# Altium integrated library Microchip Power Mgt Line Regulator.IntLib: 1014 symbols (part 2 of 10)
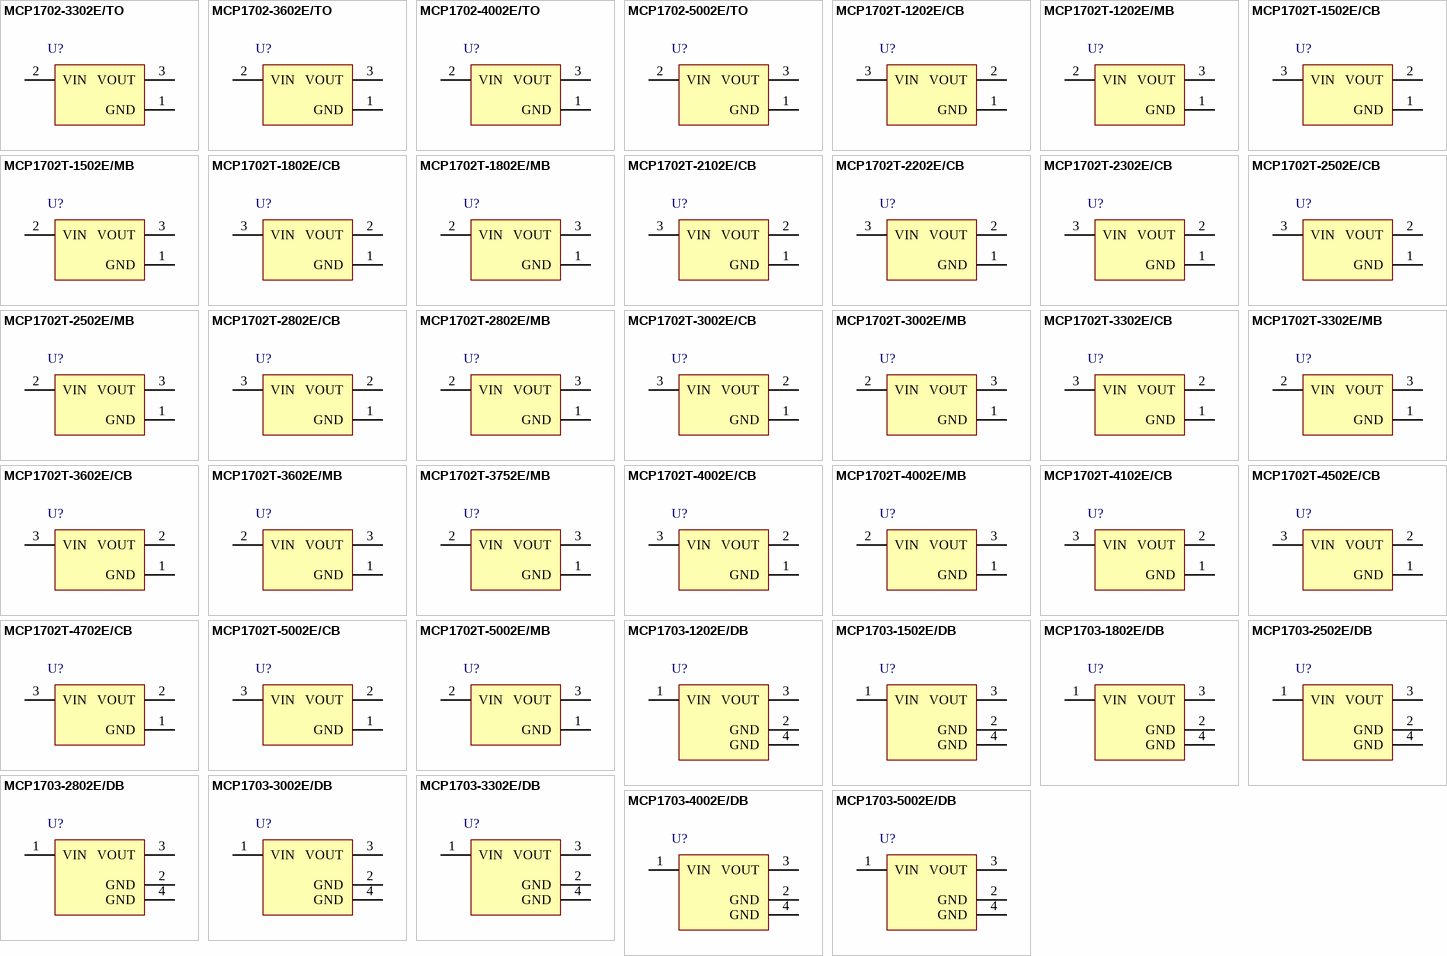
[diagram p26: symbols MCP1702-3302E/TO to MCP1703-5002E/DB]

## MCP1703-2502E/DB
designator U?
250 mA, 16V, Low Quiescent Current LDO Regulator, 3-Pin SOT-223, Extended Temperature
footprint SOT-223-DB3_N (SOT223, 4-Leads, Body 6.5x3.5mm, Pitch 2.3mm, Lead Span 7mm, IPC Medium Density)
footprint SOT-223-DB3_L (SOT223, 4-Leads, Body 6.5x3.5mm, Pitch 2.3mm, Lead Span 7mm, IPC High Density)
footprint SOT-223-DB3_M (SOT223, 4-Leads, Body 6.5x3.5mm, Pitch 2.3mm, Lead Span 7mm, IPC Low Density)
pins: 1 VIN (power), 2 GND (power), 3 VOUT (power), 4 GND (power)

## MCP1703-2802E/DB
designator U?
250 mA, 16V, Low Quiescent Current LDO Regulator, 3-Pin SOT-223, Extended Temperature
footprint SOT-223-DB3_N (SOT223, 4-Leads, Body 6.5x3.5mm, Pitch 2.3mm, Lead Span 7mm, IPC Medium Density)
footprint SOT-223-DB3_L (SOT223, 4-Leads, Body 6.5x3.5mm, Pitch 2.3mm, Lead Span 7mm, IPC High Density)
footprint SOT-223-DB3_M (SOT223, 4-Leads, Body 6.5x3.5mm, Pitch 2.3mm, Lead Span 7mm, IPC Low Density)
pins: 1 VIN (power), 2 GND (power), 3 VOUT (power), 4 GND (power)

## MCP1703-3002E/DB
designator U?
250 mA, 16V, Low Quiescent Current LDO Regulator, 3-Pin SOT-223, Extended Temperature
footprint SOT-223-DB3_N (SOT223, 4-Leads, Body 6.5x3.5mm, Pitch 2.3mm, Lead Span 7mm, IPC Medium Density)
footprint SOT-223-DB3_L (SOT223, 4-Leads, Body 6.5x3.5mm, Pitch 2.3mm, Lead Span 7mm, IPC High Density)
footprint SOT-223-DB3_M (SOT223, 4-Leads, Body 6.5x3.5mm, Pitch 2.3mm, Lead Span 7mm, IPC Low Density)
pins: 1 VIN (power), 2 GND (power), 3 VOUT (power), 4 GND (power)

## MCP1703-3302E/DB
designator U?
250 mA, 16V, Low Quiescent Current LDO Regulator, 3-Pin SOT-223, Extended Temperature
footprint SOT-223-DB3_N (SOT223, 4-Leads, Body 6.5x3.5mm, Pitch 2.3mm, Lead Span 7mm, IPC Medium Density)
footprint SOT-223-DB3_L (SOT223, 4-Leads, Body 6.5x3.5mm, Pitch 2.3mm, Lead Span 7mm, IPC High Density)
footprint SOT-223-DB3_M (SOT223, 4-Leads, Body 6.5x3.5mm, Pitch 2.3mm, Lead Span 7mm, IPC Low Density)
pins: 1 VIN (power), 2 GND (power), 3 VOUT (power), 4 GND (power)

## MCP1703-4002E/DB
designator U?
250 mA, 16V, Low Quiescent Current LDO Regulator, 3-Pin SOT-223, Extended Temperature
footprint SOT-223-DB3_N (SOT223, 4-Leads, Body 6.5x3.5mm, Pitch 2.3mm, Lead Span 7mm, IPC Medium Density)
footprint SOT-223-DB3_L (SOT223, 4-Leads, Body 6.5x3.5mm, Pitch 2.3mm, Lead Span 7mm, IPC High Density)
footprint SOT-223-DB3_M (SOT223, 4-Leads, Body 6.5x3.5mm, Pitch 2.3mm, Lead Span 7mm, IPC Low Density)
pins: 1 VIN (power), 2 GND (power), 3 VOUT (power), 4 GND (power)

## MCP1703-5002E/DB
designator U?
250 mA, 16V, Low Quiescent Current LDO Regulator, 3-Pin SOT-223, Extended Temperature
footprint SOT-223-DB3_N (SOT223, 4-Leads, Body 6.5x3.5mm, Pitch 2.3mm, Lead Span 7mm, IPC Medium Density)
footprint SOT-223-DB3_L (SOT223, 4-Leads, Body 6.5x3.5mm, Pitch 2.3mm, Lead Span 7mm, IPC High Density)
footprint SOT-223-DB3_M (SOT223, 4-Leads, Body 6.5x3.5mm, Pitch 2.3mm, Lead Span 7mm, IPC Low Density)
pins: 1 VIN (power), 2 GND (power), 3 VOUT (power), 4 GND (power)

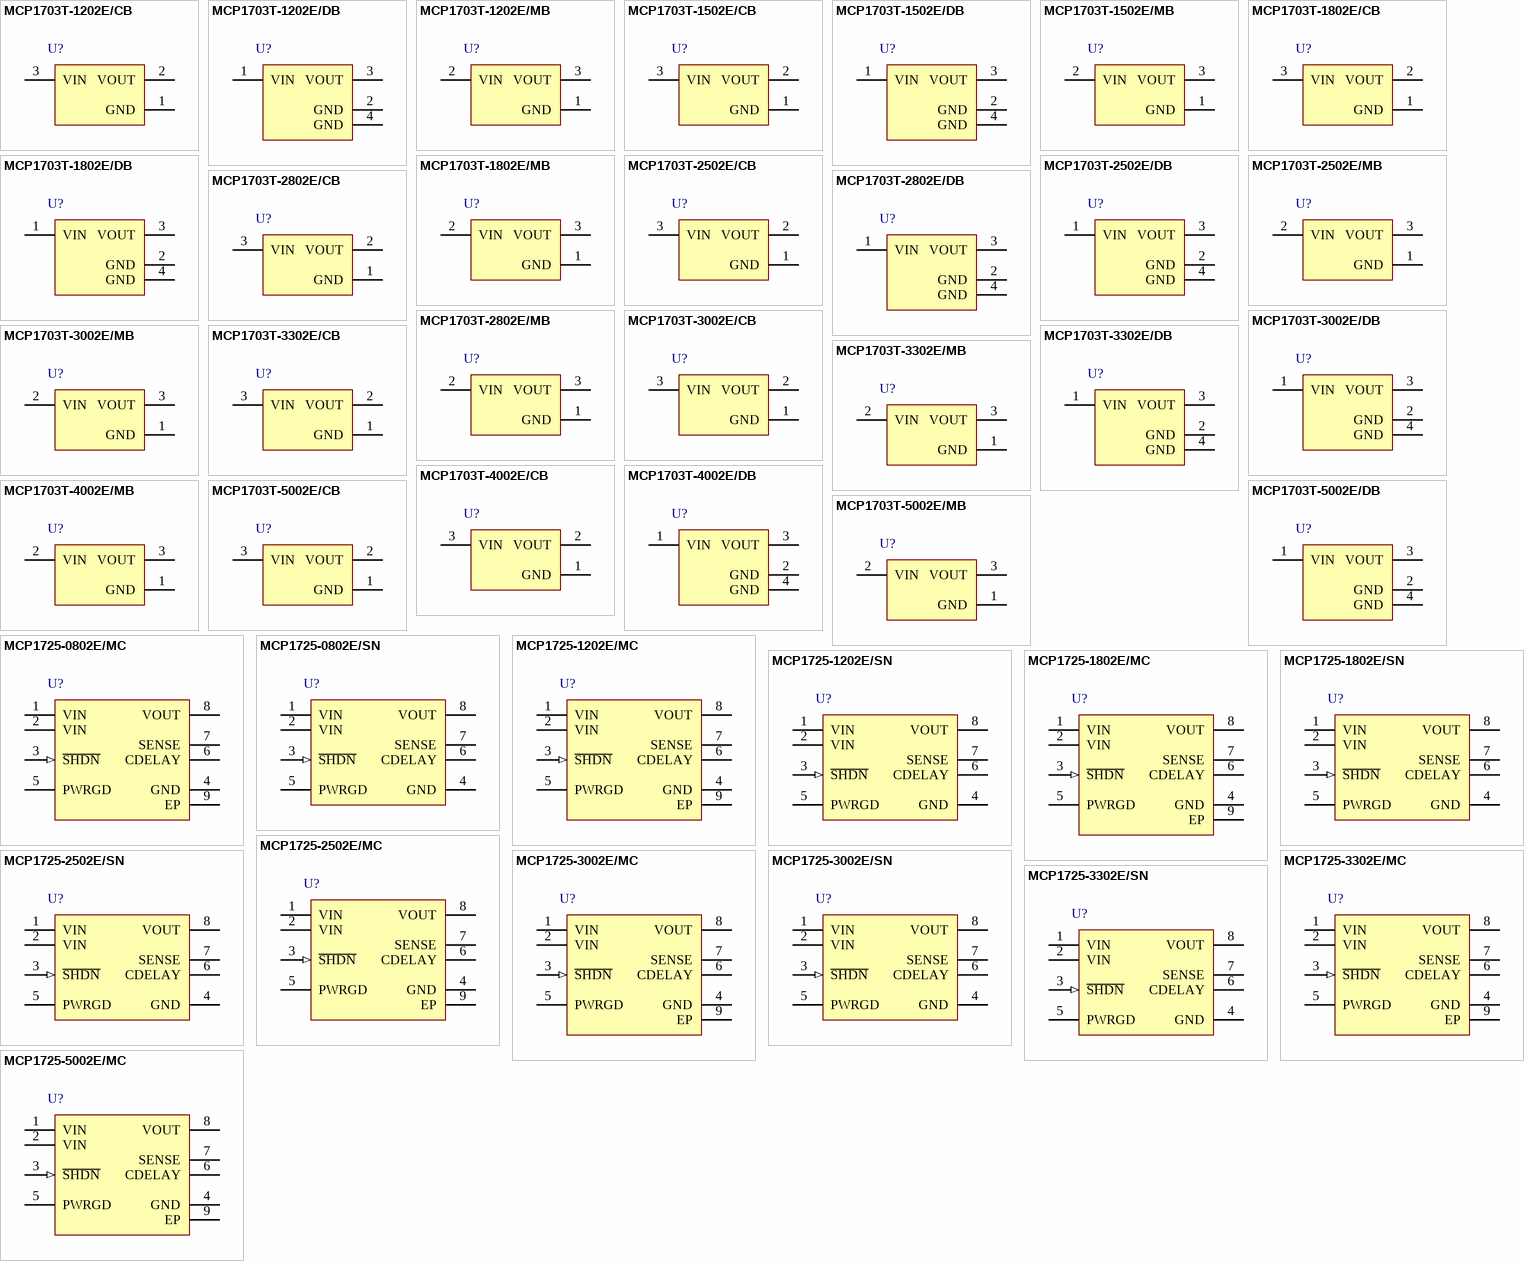
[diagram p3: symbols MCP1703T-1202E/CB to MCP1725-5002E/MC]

## MCP1703T-1202E/CB
designator U?
250 mA, 16V, Low Quiescent Current LDO Regulator, 3-Pin SOT-23A, Extended Temperature, Tape and Reel
footprint SOT-23A-CB3_N (SOT346, 3-Leads, Body 2.9x1.5mm, Pitch 0.95mm, Lead Span 2.6mm, IPC Medium Density)
footprint SOT-23A-CB3_L (SOT346, 3-Leads, Body 2.9x1.5mm, Pitch 0.95mm, Lead Span 2.6mm, IPC High Density)
footprint SOT-23A-CB3_M (SOT346, 3-Leads, Body 2.9x1.5mm, Pitch 0.95mm, Lead Span 2.6mm, IPC Low Density)
pins: 1 GND (power), 2 VOUT (power), 3 VIN (power)

## MCP1703T-1202E/DB
designator U?
250 mA, 16V, Low Quiescent Current LDO Regulator, 3-Pin SOT-223, Extended Temperature, Tape and Reel
footprint SOT-223-DB3_N (SOT223, 4-Leads, Body 6.5x3.5mm, Pitch 2.3mm, Lead Span 7mm, IPC Medium Density)
footprint SOT-223-DB3_L (SOT223, 4-Leads, Body 6.5x3.5mm, Pitch 2.3mm, Lead Span 7mm, IPC High Density)
footprint SOT-223-DB3_M (SOT223, 4-Leads, Body 6.5x3.5mm, Pitch 2.3mm, Lead Span 7mm, IPC Low Density)
pins: 1 VIN (power), 2 GND (power), 3 VOUT (power), 4 GND (power)

## MCP1703T-1202E/MB
designator U?
250 mA, 16V, Low Quiescent Current LDO Regulator, 3-Pin SOT-89, Extended Temperature, Tape and Reel
footprint SOT-89-MB3_N (SOT89, 3-Leads, Body 4.5x2.4 mm, Pitch 1.5mm, Lead Span 4.1mm, IPC Medium Density)
footprint SOT-89-MB3_L (SOT89, 3-Leads, Body 4.5x2.4 mm, Pitch 1.5mm, Lead Span 4.1mm, IPC High Density)
footprint SOT-89-MB3_M (SOT89, 3-Leads, Body 4.5x2.4 mm, Pitch 1.5mm, Lead Span 4.1mm, IPC Low Density)
pins: 1 GND (power), 2 VIN (power), 3 VOUT (power)

## MCP1703T-1502E/CB
designator U?
250 mA, 16V, Low Quiescent Current LDO Regulator, 3-Pin SOT-23A, Extended Temperature, Tape and Reel
footprint SOT-23A-CB3_N (SOT346, 3-Leads, Body 2.9x1.5mm, Pitch 0.95mm, Lead Span 2.6mm, IPC Medium Density)
footprint SOT-23A-CB3_L (SOT346, 3-Leads, Body 2.9x1.5mm, Pitch 0.95mm, Lead Span 2.6mm, IPC High Density)
footprint SOT-23A-CB3_M (SOT346, 3-Leads, Body 2.9x1.5mm, Pitch 0.95mm, Lead Span 2.6mm, IPC Low Density)
pins: 1 GND (power), 2 VOUT (power), 3 VIN (power)

## MCP1703T-1502E/DB
designator U?
250 mA, 16V, Low Quiescent Current LDO Regulator, 3-Pin SOT-223, Extended Temperature, Tape and Reel
footprint SOT-223-DB3_N (SOT223, 4-Leads, Body 6.5x3.5mm, Pitch 2.3mm, Lead Span 7mm, IPC Medium Density)
footprint SOT-223-DB3_L (SOT223, 4-Leads, Body 6.5x3.5mm, Pitch 2.3mm, Lead Span 7mm, IPC High Density)
footprint SOT-223-DB3_M (SOT223, 4-Leads, Body 6.5x3.5mm, Pitch 2.3mm, Lead Span 7mm, IPC Low Density)
pins: 1 VIN (power), 2 GND (power), 3 VOUT (power), 4 GND (power)

## MCP1703T-1502E/MB
designator U?
250 mA, 16V, Low Quiescent Current LDO Regulator, 3-Pin SOT-89, Extended Temperature, Tape and Reel
footprint SOT-89-MB3_N (SOT89, 3-Leads, Body 4.5x2.4 mm, Pitch 1.5mm, Lead Span 4.1mm, IPC Medium Density)
footprint SOT-89-MB3_L (SOT89, 3-Leads, Body 4.5x2.4 mm, Pitch 1.5mm, Lead Span 4.1mm, IPC High Density)
footprint SOT-89-MB3_M (SOT89, 3-Leads, Body 4.5x2.4 mm, Pitch 1.5mm, Lead Span 4.1mm, IPC Low Density)
pins: 1 GND (power), 2 VIN (power), 3 VOUT (power)

## MCP1703T-1802E/CB
designator U?
250 mA, 16V, Low Quiescent Current LDO Regulator, 3-Pin SOT-23A, Extended Temperature, Tape and Reel
footprint SOT-23A-CB3_N (SOT346, 3-Leads, Body 2.9x1.5mm, Pitch 0.95mm, Lead Span 2.6mm, IPC Medium Density)
footprint SOT-23A-CB3_L (SOT346, 3-Leads, Body 2.9x1.5mm, Pitch 0.95mm, Lead Span 2.6mm, IPC High Density)
footprint SOT-23A-CB3_M (SOT346, 3-Leads, Body 2.9x1.5mm, Pitch 0.95mm, Lead Span 2.6mm, IPC Low Density)
pins: 1 GND (power), 2 VOUT (power), 3 VIN (power)

## MCP1703T-1802E/DB
designator U?
250 mA, 16V, Low Quiescent Current LDO Regulator, 3-Pin SOT-223, Extended Temperature, Tape and Reel
footprint SOT-223-DB3_N (SOT223, 4-Leads, Body 6.5x3.5mm, Pitch 2.3mm, Lead Span 7mm, IPC Medium Density)
footprint SOT-223-DB3_L (SOT223, 4-Leads, Body 6.5x3.5mm, Pitch 2.3mm, Lead Span 7mm, IPC High Density)
footprint SOT-223-DB3_M (SOT223, 4-Leads, Body 6.5x3.5mm, Pitch 2.3mm, Lead Span 7mm, IPC Low Density)
pins: 1 VIN (power), 2 GND (power), 3 VOUT (power), 4 GND (power)

## MCP1703T-1802E/MB
designator U?
250 mA, 16V, Low Quiescent Current LDO Regulator, 3-Pin SOT-89, Extended Temperature, Tape and Reel
footprint SOT-89-MB3_N (SOT89, 3-Leads, Body 4.5x2.4 mm, Pitch 1.5mm, Lead Span 4.1mm, IPC Medium Density)
footprint SOT-89-MB3_L (SOT89, 3-Leads, Body 4.5x2.4 mm, Pitch 1.5mm, Lead Span 4.1mm, IPC High Density)
footprint SOT-89-MB3_M (SOT89, 3-Leads, Body 4.5x2.4 mm, Pitch 1.5mm, Lead Span 4.1mm, IPC Low Density)
pins: 1 GND (power), 2 VIN (power), 3 VOUT (power)

## MCP1703T-2502E/CB
designator U?
250 mA, 16V, Low Quiescent Current LDO Regulator, 3-Pin SOT-23A, Extended Temperature, Tape and Reel
footprint SOT-23A-CB3_N (SOT346, 3-Leads, Body 2.9x1.5mm, Pitch 0.95mm, Lead Span 2.6mm, IPC Medium Density)
footprint SOT-23A-CB3_L (SOT346, 3-Leads, Body 2.9x1.5mm, Pitch 0.95mm, Lead Span 2.6mm, IPC High Density)
footprint SOT-23A-CB3_M (SOT346, 3-Leads, Body 2.9x1.5mm, Pitch 0.95mm, Lead Span 2.6mm, IPC Low Density)
pins: 1 GND (power), 2 VOUT (power), 3 VIN (power)

## MCP1703T-2502E/DB
designator U?
250 mA, 16V, Low Quiescent Current LDO Regulator, 3-Pin SOT-223, Extended Temperature, Tape and Reel
footprint SOT-223-DB3_N (SOT223, 4-Leads, Body 6.5x3.5mm, Pitch 2.3mm, Lead Span 7mm, IPC Medium Density)
footprint SOT-223-DB3_L (SOT223, 4-Leads, Body 6.5x3.5mm, Pitch 2.3mm, Lead Span 7mm, IPC High Density)
footprint SOT-223-DB3_M (SOT223, 4-Leads, Body 6.5x3.5mm, Pitch 2.3mm, Lead Span 7mm, IPC Low Density)
pins: 1 VIN (power), 2 GND (power), 3 VOUT (power), 4 GND (power)

## MCP1703T-2502E/MB
designator U?
250 mA, 16V, Low Quiescent Current LDO Regulator, 3-Pin SOT-89, Extended Temperature, Tape and Reel
footprint SOT-89-MB3_N (SOT89, 3-Leads, Body 4.5x2.4 mm, Pitch 1.5mm, Lead Span 4.1mm, IPC Medium Density)
footprint SOT-89-MB3_L (SOT89, 3-Leads, Body 4.5x2.4 mm, Pitch 1.5mm, Lead Span 4.1mm, IPC High Density)
footprint SOT-89-MB3_M (SOT89, 3-Leads, Body 4.5x2.4 mm, Pitch 1.5mm, Lead Span 4.1mm, IPC Low Density)
pins: 1 GND (power), 2 VIN (power), 3 VOUT (power)

## MCP1703T-2802E/CB
designator U?
250 mA, 16V, Low Quiescent Current LDO Regulator, 3-Pin SOT-23A, Extended Temperature, Tape and Reel
footprint SOT-23A-CB3_N (SOT346, 3-Leads, Body 2.9x1.5mm, Pitch 0.95mm, Lead Span 2.6mm, IPC Medium Density)
footprint SOT-23A-CB3_L (SOT346, 3-Leads, Body 2.9x1.5mm, Pitch 0.95mm, Lead Span 2.6mm, IPC High Density)
footprint SOT-23A-CB3_M (SOT346, 3-Leads, Body 2.9x1.5mm, Pitch 0.95mm, Lead Span 2.6mm, IPC Low Density)
pins: 1 GND (power), 2 VOUT (power), 3 VIN (power)

## MCP1703T-2802E/DB
designator U?
250 mA, 16V, Low Quiescent Current LDO Regulator, 3-Pin SOT-223, Extended Temperature, Tape and Reel
footprint SOT-223-DB3_N (SOT223, 4-Leads, Body 6.5x3.5mm, Pitch 2.3mm, Lead Span 7mm, IPC Medium Density)
footprint SOT-223-DB3_L (SOT223, 4-Leads, Body 6.5x3.5mm, Pitch 2.3mm, Lead Span 7mm, IPC High Density)
footprint SOT-223-DB3_M (SOT223, 4-Leads, Body 6.5x3.5mm, Pitch 2.3mm, Lead Span 7mm, IPC Low Density)
pins: 1 VIN (power), 2 GND (power), 3 VOUT (power), 4 GND (power)

## MCP1703T-2802E/MB
designator U?
250 mA, 16V, Low Quiescent Current LDO Regulator, 3-Pin SOT-89, Extended Temperature, Tape and Reel
footprint SOT-89-MB3_N (SOT89, 3-Leads, Body 4.5x2.4 mm, Pitch 1.5mm, Lead Span 4.1mm, IPC Medium Density)
footprint SOT-89-MB3_L (SOT89, 3-Leads, Body 4.5x2.4 mm, Pitch 1.5mm, Lead Span 4.1mm, IPC High Density)
footprint SOT-89-MB3_M (SOT89, 3-Leads, Body 4.5x2.4 mm, Pitch 1.5mm, Lead Span 4.1mm, IPC Low Density)
pins: 1 GND (power), 2 VIN (power), 3 VOUT (power)

## MCP1703T-3002E/CB
designator U?
250 mA, 16V, Low Quiescent Current LDO Regulator, 3-Pin SOT-23A, Extended Temperature, Tape and Reel
footprint SOT-23A-CB3_N (SOT346, 3-Leads, Body 2.9x1.5mm, Pitch 0.95mm, Lead Span 2.6mm, IPC Medium Density)
footprint SOT-23A-CB3_L (SOT346, 3-Leads, Body 2.9x1.5mm, Pitch 0.95mm, Lead Span 2.6mm, IPC High Density)
footprint SOT-23A-CB3_M (SOT346, 3-Leads, Body 2.9x1.5mm, Pitch 0.95mm, Lead Span 2.6mm, IPC Low Density)
pins: 1 GND (power), 2 VOUT (power), 3 VIN (power)

## MCP1703T-3002E/DB
designator U?
250 mA, 16V, Low Quiescent Current LDO Regulator, 3-Pin SOT-223, Extended Temperature, Tape and Reel
footprint SOT-223-DB3_N (SOT223, 4-Leads, Body 6.5x3.5mm, Pitch 2.3mm, Lead Span 7mm, IPC Medium Density)
footprint SOT-223-DB3_L (SOT223, 4-Leads, Body 6.5x3.5mm, Pitch 2.3mm, Lead Span 7mm, IPC High Density)
footprint SOT-223-DB3_M (SOT223, 4-Leads, Body 6.5x3.5mm, Pitch 2.3mm, Lead Span 7mm, IPC Low Density)
pins: 1 VIN (power), 2 GND (power), 3 VOUT (power), 4 GND (power)

## MCP1703T-3002E/MB
designator U?
250 mA, 16V, Low Quiescent Current LDO Regulator, 3-Pin SOT-89, Extended Temperature, Tape and Reel
footprint SOT-89-MB3_N (SOT89, 3-Leads, Body 4.5x2.4 mm, Pitch 1.5mm, Lead Span 4.1mm, IPC Medium Density)
footprint SOT-89-MB3_L (SOT89, 3-Leads, Body 4.5x2.4 mm, Pitch 1.5mm, Lead Span 4.1mm, IPC High Density)
footprint SOT-89-MB3_M (SOT89, 3-Leads, Body 4.5x2.4 mm, Pitch 1.5mm, Lead Span 4.1mm, IPC Low Density)
pins: 1 GND (power), 2 VIN (power), 3 VOUT (power)

## MCP1703T-3302E/CB
designator U?
250 mA, 16V, Low Quiescent Current LDO Regulator, 3-Pin SOT-23A, Extended Temperature, Tape and Reel
footprint SOT-23A-CB3_N (SOT346, 3-Leads, Body 2.9x1.5mm, Pitch 0.95mm, Lead Span 2.6mm, IPC Medium Density)
footprint SOT-23A-CB3_L (SOT346, 3-Leads, Body 2.9x1.5mm, Pitch 0.95mm, Lead Span 2.6mm, IPC High Density)
footprint SOT-23A-CB3_M (SOT346, 3-Leads, Body 2.9x1.5mm, Pitch 0.95mm, Lead Span 2.6mm, IPC Low Density)
pins: 1 GND (power), 2 VOUT (power), 3 VIN (power)

## MCP1703T-3302E/DB
designator U?
250 mA, 16V, Low Quiescent Current LDO Regulator, 3-Pin SOT-223, Extended Temperature, Tape and Reel
footprint SOT-223-DB3_N (SOT223, 4-Leads, Body 6.5x3.5mm, Pitch 2.3mm, Lead Span 7mm, IPC Medium Density)
footprint SOT-223-DB3_L (SOT223, 4-Leads, Body 6.5x3.5mm, Pitch 2.3mm, Lead Span 7mm, IPC High Density)
footprint SOT-223-DB3_M (SOT223, 4-Leads, Body 6.5x3.5mm, Pitch 2.3mm, Lead Span 7mm, IPC Low Density)
pins: 1 VIN (power), 2 GND (power), 3 VOUT (power), 4 GND (power)

## MCP1703T-3302E/MB
designator U?
250 mA, 16V, Low Quiescent Current LDO Regulator, 3-Pin SOT-89, Extended Temperature, Tape and Reel
footprint SOT-89-MB3_N (SOT89, 3-Leads, Body 4.5x2.4 mm, Pitch 1.5mm, Lead Span 4.1mm, IPC Medium Density)
footprint SOT-89-MB3_L (SOT89, 3-Leads, Body 4.5x2.4 mm, Pitch 1.5mm, Lead Span 4.1mm, IPC High Density)
footprint SOT-89-MB3_M (SOT89, 3-Leads, Body 4.5x2.4 mm, Pitch 1.5mm, Lead Span 4.1mm, IPC Low Density)
pins: 1 GND (power), 2 VIN (power), 3 VOUT (power)

## MCP1703T-4002E/CB
designator U?
250 mA, 16V, Low Quiescent Current LDO Regulator, 3-Pin SOT-23A, Extended Temperature, Tape and Reel
footprint SOT-23A-CB3_N (SOT346, 3-Leads, Body 2.9x1.5mm, Pitch 0.95mm, Lead Span 2.6mm, IPC Medium Density)
footprint SOT-23A-CB3_L (SOT346, 3-Leads, Body 2.9x1.5mm, Pitch 0.95mm, Lead Span 2.6mm, IPC High Density)
footprint SOT-23A-CB3_M (SOT346, 3-Leads, Body 2.9x1.5mm, Pitch 0.95mm, Lead Span 2.6mm, IPC Low Density)
pins: 1 GND (power), 2 VOUT (power), 3 VIN (power)

## MCP1703T-4002E/DB
designator U?
250 mA, 16V, Low Quiescent Current LDO Regulator, 3-Pin SOT-223, Extended Temperature, Tape and Reel
footprint SOT-223-DB3_N (SOT223, 4-Leads, Body 6.5x3.5mm, Pitch 2.3mm, Lead Span 7mm, IPC Medium Density)
footprint SOT-223-DB3_L (SOT223, 4-Leads, Body 6.5x3.5mm, Pitch 2.3mm, Lead Span 7mm, IPC High Density)
footprint SOT-223-DB3_M (SOT223, 4-Leads, Body 6.5x3.5mm, Pitch 2.3mm, Lead Span 7mm, IPC Low Density)
pins: 1 VIN (power), 2 GND (power), 3 VOUT (power), 4 GND (power)

## MCP1703T-4002E/MB
designator U?
250 mA, 16V, Low Quiescent Current LDO Regulator, 3-Pin SOT-89, Extended Temperature, Tape and Reel
footprint SOT-89-MB3_N (SOT89, 3-Leads, Body 4.5x2.4 mm, Pitch 1.5mm, Lead Span 4.1mm, IPC Medium Density)
footprint SOT-89-MB3_L (SOT89, 3-Leads, Body 4.5x2.4 mm, Pitch 1.5mm, Lead Span 4.1mm, IPC High Density)
footprint SOT-89-MB3_M (SOT89, 3-Leads, Body 4.5x2.4 mm, Pitch 1.5mm, Lead Span 4.1mm, IPC Low Density)
pins: 1 GND (power), 2 VIN (power), 3 VOUT (power)

## MCP1703T-5002E/CB
designator U?
250 mA, 16V, Low Quiescent Current LDO Regulator, 3-Pin SOT-23A, Extended Temperature, Tape and Reel
footprint SOT-23A-CB3_N (SOT346, 3-Leads, Body 2.9x1.5mm, Pitch 0.95mm, Lead Span 2.6mm, IPC Medium Density)
footprint SOT-23A-CB3_L (SOT346, 3-Leads, Body 2.9x1.5mm, Pitch 0.95mm, Lead Span 2.6mm, IPC High Density)
footprint SOT-23A-CB3_M (SOT346, 3-Leads, Body 2.9x1.5mm, Pitch 0.95mm, Lead Span 2.6mm, IPC Low Density)
pins: 1 GND (power), 2 VOUT (power), 3 VIN (power)

## MCP1703T-5002E/DB
designator U?
250 mA, 16V, Low Quiescent Current LDO Regulator, 3-Pin SOT-223, Extended Temperature, Tape and Reel
footprint SOT-223-DB3_N (SOT223, 4-Leads, Body 6.5x3.5mm, Pitch 2.3mm, Lead Span 7mm, IPC Medium Density)
footprint SOT-223-DB3_L (SOT223, 4-Leads, Body 6.5x3.5mm, Pitch 2.3mm, Lead Span 7mm, IPC High Density)
footprint SOT-223-DB3_M (SOT223, 4-Leads, Body 6.5x3.5mm, Pitch 2.3mm, Lead Span 7mm, IPC Low Density)
pins: 1 VIN (power), 2 GND (power), 3 VOUT (power), 4 GND (power)

## MCP1703T-5002E/MB
designator U?
250 mA, 16V, Low Quiescent Current LDO Regulator, 3-Pin SOT-89, Extended Temperature, Tape and Reel
footprint SOT-89-MB3_N (SOT89, 3-Leads, Body 4.5x2.4 mm, Pitch 1.5mm, Lead Span 4.1mm, IPC Medium Density)
footprint SOT-89-MB3_L (SOT89, 3-Leads, Body 4.5x2.4 mm, Pitch 1.5mm, Lead Span 4.1mm, IPC High Density)
footprint SOT-89-MB3_M (SOT89, 3-Leads, Body 4.5x2.4 mm, Pitch 1.5mm, Lead Span 4.1mm, IPC Low Density)
pins: 1 GND (power), 2 VIN (power), 3 VOUT (power)

## MCP1725-0802E/MC
designator U?
500 mA, Low Voltage, Low Quiescent Current LDO Regulator, 8-Pin DFN, Extended Temperature
footprint DFN-MC8 (SON, 8-Leads, Body 2x3mm, Pitch 0.5mm, Microchip Recommended)
pins: 1 VIN (power), 2 VIN (power), 3 ~{SHDN} (in), 4 GND (power), 5 PWRGD (power), 6 CDELAY, 7 SENSE, 8 VOUT (power), 9 EP (power)

## MCP1725-0802E/SN
designator U?
500 mA, Low Voltage, Low Quiescent Current LDO Regulator, 8-Pin SOIC 150mil, Extended Temperature
footprint SOIC-SN8_N (SOIC, 8-Leads, Body 4.9x3.8mm, Pitch 1.27mm, IPC Medium Density)
footprint SOIC-SN8_L (SOIC, 8-Leads, Body 4.9x3.8mm, Pitch 1.27mm, IPC High Density)
footprint SOIC-SN8_M (SOIC, 8-Leads, Body 4.9x3.8mm, Pitch 1.27mm, IPC Low Density)
pins: 1 VIN (power), 2 VIN (power), 3 ~{SHDN} (in), 4 GND (power), 5 PWRGD (power), 6 CDELAY, 7 SENSE, 8 VOUT (power)

## MCP1725-1202E/MC
designator U?
500 mA, Low Voltage, Low Quiescent Current LDO Regulator, 8-Pin DFN, Extended Temperature
footprint DFN-MC8 (SON, 8-Leads, Body 2x3mm, Pitch 0.5mm, Microchip Recommended)
pins: 1 VIN (power), 2 VIN (power), 3 ~{SHDN} (in), 4 GND (power), 5 PWRGD (power), 6 CDELAY, 7 SENSE, 8 VOUT (power), 9 EP (power)

## MCP1725-1202E/SN
designator U?
500 mA, Low Voltage, Low Quiescent Current LDO Regulator, 8-Pin SOIC 150mil, Extended Temperature
footprint SOIC-SN8_N (SOIC, 8-Leads, Body 4.9x3.8mm, Pitch 1.27mm, IPC Medium Density)
footprint SOIC-SN8_L (SOIC, 8-Leads, Body 4.9x3.8mm, Pitch 1.27mm, IPC High Density)
footprint SOIC-SN8_M (SOIC, 8-Leads, Body 4.9x3.8mm, Pitch 1.27mm, IPC Low Density)
pins: 1 VIN (power), 2 VIN (power), 3 ~{SHDN} (in), 4 GND (power), 5 PWRGD (power), 6 CDELAY, 7 SENSE, 8 VOUT (power)

## MCP1725-1802E/MC
designator U?
500 mA, Low Voltage, Low Quiescent Current LDO Regulator, 8-Pin DFN, Extended Temperature
footprint DFN-MC8 (SON, 8-Leads, Body 2x3mm, Pitch 0.5mm, Microchip Recommended)
pins: 1 VIN (power), 2 VIN (power), 3 ~{SHDN} (in), 4 GND (power), 5 PWRGD (power), 6 CDELAY, 7 SENSE, 8 VOUT (power), 9 EP (power)

## MCP1725-1802E/SN
designator U?
500 mA, Low Voltage, Low Quiescent Current LDO Regulator, 8-Pin SOIC 150mil, Extended Temperature
footprint SOIC-SN8_N (SOIC, 8-Leads, Body 4.9x3.8mm, Pitch 1.27mm, IPC Medium Density)
footprint SOIC-SN8_L (SOIC, 8-Leads, Body 4.9x3.8mm, Pitch 1.27mm, IPC High Density)
footprint SOIC-SN8_M (SOIC, 8-Leads, Body 4.9x3.8mm, Pitch 1.27mm, IPC Low Density)
pins: 1 VIN (power), 2 VIN (power), 3 ~{SHDN} (in), 4 GND (power), 5 PWRGD (power), 6 CDELAY, 7 SENSE, 8 VOUT (power)

## MCP1725-2502E/MC
designator U?
500 mA, Low Voltage, Low Quiescent Current LDO Regulator, 8-Pin DFN, Extended Temperature
footprint DFN-MC8 (SON, 8-Leads, Body 2x3mm, Pitch 0.5mm, Microchip Recommended)
pins: 1 VIN (power), 2 VIN (power), 3 ~{SHDN} (in), 4 GND (power), 5 PWRGD (power), 6 CDELAY, 7 SENSE, 8 VOUT (power), 9 EP (power)

## MCP1725-2502E/SN
designator U?
500 mA, Low Voltage, Low Quiescent Current LDO Regulator, 8-Pin SOIC 150mil, Extended Temperature
footprint SOIC-SN8_N (SOIC, 8-Leads, Body 4.9x3.8mm, Pitch 1.27mm, IPC Medium Density)
footprint SOIC-SN8_L (SOIC, 8-Leads, Body 4.9x3.8mm, Pitch 1.27mm, IPC High Density)
footprint SOIC-SN8_M (SOIC, 8-Leads, Body 4.9x3.8mm, Pitch 1.27mm, IPC Low Density)
pins: 1 VIN (power), 2 VIN (power), 3 ~{SHDN} (in), 4 GND (power), 5 PWRGD (power), 6 CDELAY, 7 SENSE, 8 VOUT (power)

## MCP1725-3002E/MC
designator U?
500 mA, Low Voltage, Low Quiescent Current LDO Regulator, 8-Pin DFN, Extended Temperature
footprint DFN-MC8 (SON, 8-Leads, Body 2x3mm, Pitch 0.5mm, Microchip Recommended)
pins: 1 VIN (power), 2 VIN (power), 3 ~{SHDN} (in), 4 GND (power), 5 PWRGD (power), 6 CDELAY, 7 SENSE, 8 VOUT (power), 9 EP (power)

## MCP1725-3002E/SN
designator U?
500 mA, Low Voltage, Low Quiescent Current LDO Regulator, 8-Pin SOIC 150mil, Extended Temperature
footprint SOIC-SN8_N (SOIC, 8-Leads, Body 4.9x3.8mm, Pitch 1.27mm, IPC Medium Density)
footprint SOIC-SN8_L (SOIC, 8-Leads, Body 4.9x3.8mm, Pitch 1.27mm, IPC High Density)
footprint SOIC-SN8_M (SOIC, 8-Leads, Body 4.9x3.8mm, Pitch 1.27mm, IPC Low Density)
pins: 1 VIN (power), 2 VIN (power), 3 ~{SHDN} (in), 4 GND (power), 5 PWRGD (power), 6 CDELAY, 7 SENSE, 8 VOUT (power)

## MCP1725-3302E/MC
designator U?
500 mA, Low Voltage, Low Quiescent Current LDO Regulator, 8-Pin DFN, Extended Temperature
footprint DFN-MC8 (SON, 8-Leads, Body 2x3mm, Pitch 0.5mm, Microchip Recommended)
pins: 1 VIN (power), 2 VIN (power), 3 ~{SHDN} (in), 4 GND (power), 5 PWRGD (power), 6 CDELAY, 7 SENSE, 8 VOUT (power), 9 EP (power)

## MCP1725-3302E/SN
designator U?
500 mA, Low Voltage, Low Quiescent Current LDO Regulator, 8-Pin SOIC 150mil, Extended Temperature
footprint SOIC-SN8_N (SOIC, 8-Leads, Body 4.9x3.8mm, Pitch 1.27mm, IPC Medium Density)
footprint SOIC-SN8_L (SOIC, 8-Leads, Body 4.9x3.8mm, Pitch 1.27mm, IPC High Density)
footprint SOIC-SN8_M (SOIC, 8-Leads, Body 4.9x3.8mm, Pitch 1.27mm, IPC Low Density)
pins: 1 VIN (power), 2 VIN (power), 3 ~{SHDN} (in), 4 GND (power), 5 PWRGD (power), 6 CDELAY, 7 SENSE, 8 VOUT (power)

## MCP1725-5002E/MC
designator U?
500 mA, Low Voltage, Low Quiescent Current LDO Regulator, 8-Pin DFN, Extended Temperature
footprint DFN-MC8 (SON, 8-Leads, Body 2x3mm, Pitch 0.5mm, Microchip Recommended)
pins: 1 VIN (power), 2 VIN (power), 3 ~{SHDN} (in), 4 GND (power), 5 PWRGD (power), 6 CDELAY, 7 SENSE, 8 VOUT (power), 9 EP (power)

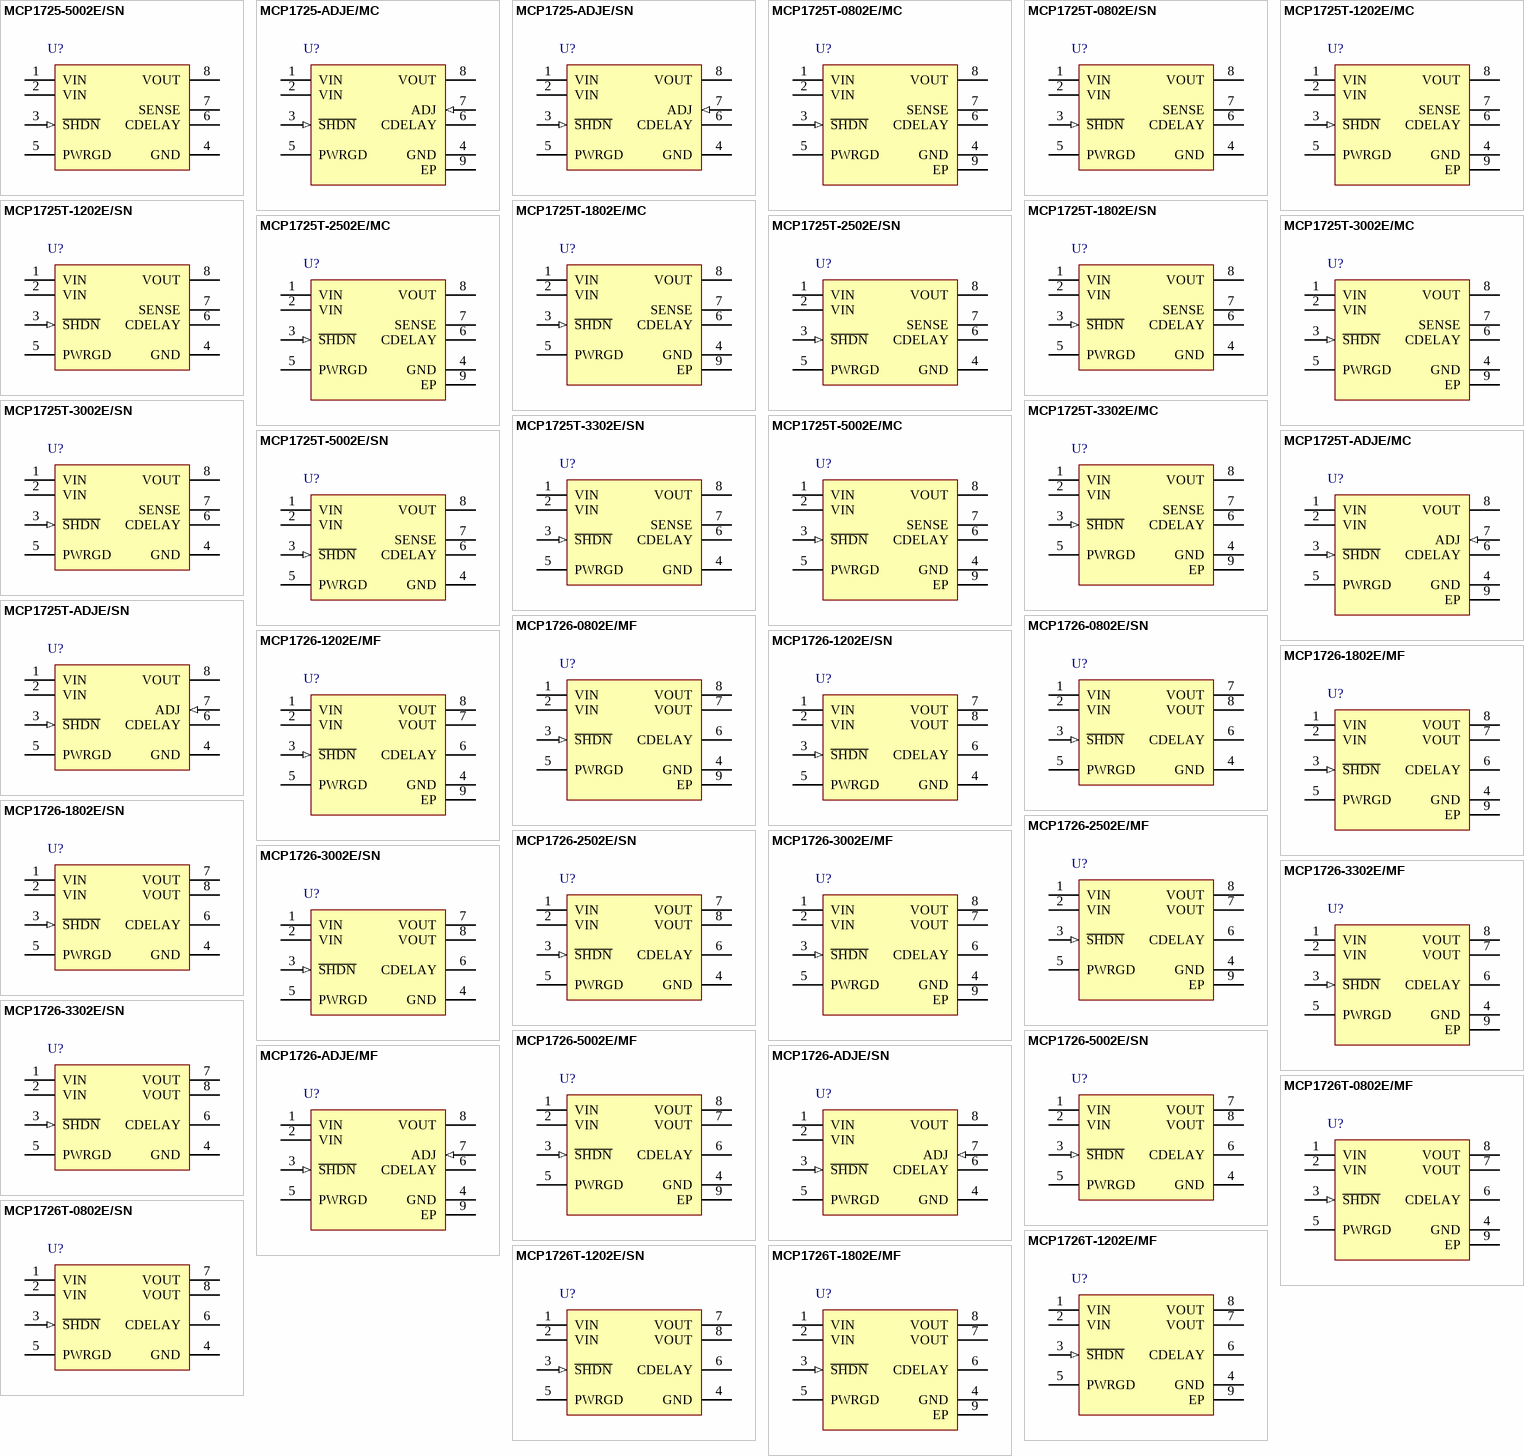
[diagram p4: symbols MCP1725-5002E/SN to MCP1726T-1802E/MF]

## MCP1725-5002E/SN
designator U?
500 mA, Low Voltage, Low Quiescent Current LDO Regulator, 8-Pin SOIC 150mil, Extended Temperature
footprint SOIC-SN8_N (SOIC, 8-Leads, Body 4.9x3.8mm, Pitch 1.27mm, IPC Medium Density)
footprint SOIC-SN8_L (SOIC, 8-Leads, Body 4.9x3.8mm, Pitch 1.27mm, IPC High Density)
footprint SOIC-SN8_M (SOIC, 8-Leads, Body 4.9x3.8mm, Pitch 1.27mm, IPC Low Density)
pins: 1 VIN (power), 2 VIN (power), 3 ~{SHDN} (in), 4 GND (power), 5 PWRGD (power), 6 CDELAY, 7 SENSE, 8 VOUT (power)

## MCP1725-ADJE/MC
designator U?
500 mA, Low Voltage, Low Quiescent Current LDO Regulator, 8-Pin DFN, Extended Temperature
footprint DFN-MC8 (SON, 8-Leads, Body 2x3mm, Pitch 0.5mm, Microchip Recommended)
pins: 1 VIN (power), 2 VIN (power), 3 ~{SHDN} (in), 4 GND (power), 5 PWRGD (power), 6 CDELAY, 7 ADJ (in), 8 VOUT (power), 9 EP (power)

## MCP1725-ADJE/SN
designator U?
500 mA, Low Voltage, Low Quiescent Current LDO Regulator, 8-Pin SOIC 150mil, Extended Temperature
footprint SOIC-SN8_N (SOIC, 8-Leads, Body 4.9x3.8mm, Pitch 1.27mm, IPC Medium Density)
footprint SOIC-SN8_L (SOIC, 8-Leads, Body 4.9x3.8mm, Pitch 1.27mm, IPC High Density)
footprint SOIC-SN8_M (SOIC, 8-Leads, Body 4.9x3.8mm, Pitch 1.27mm, IPC Low Density)
pins: 1 VIN (power), 2 VIN (power), 3 ~{SHDN} (in), 4 GND (power), 5 PWRGD (power), 6 CDELAY, 7 ADJ (in), 8 VOUT (power)

## MCP1725T-0802E/MC
designator U?
500 mA, Low Voltage, Low Quiescent Current LDO Regulator, 8-Pin DFN, Extended Temperature, Tape and Reel
footprint DFN-MC8 (SON, 8-Leads, Body 2x3mm, Pitch 0.5mm, Microchip Recommended)
pins: 1 VIN (power), 2 VIN (power), 3 ~{SHDN} (in), 4 GND (power), 5 PWRGD (power), 6 CDELAY, 7 SENSE, 8 VOUT (power), 9 EP (power)

## MCP1725T-0802E/SN
designator U?
500 mA, Low Voltage, Low Quiescent Current LDO Regulator, 8-Pin SOIC 150mil, Extended Temperature, Tape and Reel
footprint SOIC-SN8_N (SOIC, 8-Leads, Body 4.9x3.8mm, Pitch 1.27mm, IPC Medium Density)
footprint SOIC-SN8_L (SOIC, 8-Leads, Body 4.9x3.8mm, Pitch 1.27mm, IPC High Density)
footprint SOIC-SN8_M (SOIC, 8-Leads, Body 4.9x3.8mm, Pitch 1.27mm, IPC Low Density)
pins: 1 VIN (power), 2 VIN (power), 3 ~{SHDN} (in), 4 GND (power), 5 PWRGD (power), 6 CDELAY, 7 SENSE, 8 VOUT (power)

## MCP1725T-1202E/MC
designator U?
500 mA, Low Voltage, Low Quiescent Current LDO Regulator, 8-Pin DFN, Extended Temperature, Tape and Reel
footprint DFN-MC8 (SON, 8-Leads, Body 2x3mm, Pitch 0.5mm, Microchip Recommended)
pins: 1 VIN (power), 2 VIN (power), 3 ~{SHDN} (in), 4 GND (power), 5 PWRGD (power), 6 CDELAY, 7 SENSE, 8 VOUT (power), 9 EP (power)

## MCP1725T-1202E/SN
designator U?
500 mA, Low Voltage, Low Quiescent Current LDO Regulator, 8-Pin SOIC 150mil, Extended Temperature, Tape and Reel
footprint SOIC-SN8_N (SOIC, 8-Leads, Body 4.9x3.8mm, Pitch 1.27mm, IPC Medium Density)
footprint SOIC-SN8_L (SOIC, 8-Leads, Body 4.9x3.8mm, Pitch 1.27mm, IPC High Density)
footprint SOIC-SN8_M (SOIC, 8-Leads, Body 4.9x3.8mm, Pitch 1.27mm, IPC Low Density)
pins: 1 VIN (power), 2 VIN (power), 3 ~{SHDN} (in), 4 GND (power), 5 PWRGD (power), 6 CDELAY, 7 SENSE, 8 VOUT (power)

## MCP1725T-1802E/MC
designator U?
500 mA, Low Voltage, Low Quiescent Current LDO Regulator, 8-Pin DFN, Extended Temperature, Tape and Reel
footprint DFN-MC8 (SON, 8-Leads, Body 2x3mm, Pitch 0.5mm, Microchip Recommended)
pins: 1 VIN (power), 2 VIN (power), 3 ~{SHDN} (in), 4 GND (power), 5 PWRGD (power), 6 CDELAY, 7 SENSE, 8 VOUT (power), 9 EP (power)

## MCP1725T-1802E/SN
designator U?
500 mA, Low Voltage, Low Quiescent Current LDO Regulator, 8-Pin SOIC 150mil, Extended Temperature, Tape and Reel
footprint SOIC-SN8_N (SOIC, 8-Leads, Body 4.9x3.8mm, Pitch 1.27mm, IPC Medium Density)
footprint SOIC-SN8_L (SOIC, 8-Leads, Body 4.9x3.8mm, Pitch 1.27mm, IPC High Density)
footprint SOIC-SN8_M (SOIC, 8-Leads, Body 4.9x3.8mm, Pitch 1.27mm, IPC Low Density)
pins: 1 VIN (power), 2 VIN (power), 3 ~{SHDN} (in), 4 GND (power), 5 PWRGD (power), 6 CDELAY, 7 SENSE, 8 VOUT (power)

## MCP1725T-2502E/MC
designator U?
500 mA, Low Voltage, Low Quiescent Current LDO Regulator, 8-Pin DFN, Extended Temperature, Tape and Reel
footprint DFN-MC8 (SON, 8-Leads, Body 2x3mm, Pitch 0.5mm, Microchip Recommended)
pins: 1 VIN (power), 2 VIN (power), 3 ~{SHDN} (in), 4 GND (power), 5 PWRGD (power), 6 CDELAY, 7 SENSE, 8 VOUT (power), 9 EP (power)

## MCP1725T-2502E/SN
designator U?
500 mA, Low Voltage, Low Quiescent Current LDO Regulator, 8-Pin SOIC 150mil, Extended Temperature, Tape and Reel
footprint SOIC-SN8_N (SOIC, 8-Leads, Body 4.9x3.8mm, Pitch 1.27mm, IPC Medium Density)
footprint SOIC-SN8_L (SOIC, 8-Leads, Body 4.9x3.8mm, Pitch 1.27mm, IPC High Density)
footprint SOIC-SN8_M (SOIC, 8-Leads, Body 4.9x3.8mm, Pitch 1.27mm, IPC Low Density)
pins: 1 VIN (power), 2 VIN (power), 3 ~{SHDN} (in), 4 GND (power), 5 PWRGD (power), 6 CDELAY, 7 SENSE, 8 VOUT (power)

## MCP1725T-3002E/MC
designator U?
500 mA, Low Voltage, Low Quiescent Current LDO Regulator, 8-Pin DFN, Extended Temperature, Tape and Reel
footprint DFN-MC8 (SON, 8-Leads, Body 2x3mm, Pitch 0.5mm, Microchip Recommended)
pins: 1 VIN (power), 2 VIN (power), 3 ~{SHDN} (in), 4 GND (power), 5 PWRGD (power), 6 CDELAY, 7 SENSE, 8 VOUT (power), 9 EP (power)

## MCP1725T-3002E/SN
designator U?
500 mA, Low Voltage, Low Quiescent Current LDO Regulator, 8-Pin SOIC 150mil, Extended Temperature, Tape and Reel
footprint SOIC-SN8_N (SOIC, 8-Leads, Body 4.9x3.8mm, Pitch 1.27mm, IPC Medium Density)
footprint SOIC-SN8_L (SOIC, 8-Leads, Body 4.9x3.8mm, Pitch 1.27mm, IPC High Density)
footprint SOIC-SN8_M (SOIC, 8-Leads, Body 4.9x3.8mm, Pitch 1.27mm, IPC Low Density)
pins: 1 VIN (power), 2 VIN (power), 3 ~{SHDN} (in), 4 GND (power), 5 PWRGD (power), 6 CDELAY, 7 SENSE, 8 VOUT (power)

## MCP1725T-3302E/MC
designator U?
500 mA, Low Voltage, Low Quiescent Current LDO Regulator, 8-Pin DFN, Extended Temperature, Tape and Reel
footprint DFN-MC8 (SON, 8-Leads, Body 2x3mm, Pitch 0.5mm, Microchip Recommended)
pins: 1 VIN (power), 2 VIN (power), 3 ~{SHDN} (in), 4 GND (power), 5 PWRGD (power), 6 CDELAY, 7 SENSE, 8 VOUT (power), 9 EP (power)

## MCP1725T-3302E/SN
designator U?
500 mA, Low Voltage, Low Quiescent Current LDO Regulator, 8-Pin SOIC 150mil, Extended Temperature, Tape and Reel
footprint SOIC-SN8_N (SOIC, 8-Leads, Body 4.9x3.8mm, Pitch 1.27mm, IPC Medium Density)
footprint SOIC-SN8_L (SOIC, 8-Leads, Body 4.9x3.8mm, Pitch 1.27mm, IPC High Density)
footprint SOIC-SN8_M (SOIC, 8-Leads, Body 4.9x3.8mm, Pitch 1.27mm, IPC Low Density)
pins: 1 VIN (power), 2 VIN (power), 3 ~{SHDN} (in), 4 GND (power), 5 PWRGD (power), 6 CDELAY, 7 SENSE, 8 VOUT (power)

## MCP1725T-5002E/MC
designator U?
500 mA, Low Voltage, Low Quiescent Current LDO Regulator, 8-Pin DFN, Extended Temperature, Tape and Reel
footprint DFN-MC8 (SON, 8-Leads, Body 2x3mm, Pitch 0.5mm, Microchip Recommended)
pins: 1 VIN (power), 2 VIN (power), 3 ~{SHDN} (in), 4 GND (power), 5 PWRGD (power), 6 CDELAY, 7 SENSE, 8 VOUT (power), 9 EP (power)

## MCP1725T-5002E/SN
designator U?
500 mA, Low Voltage, Low Quiescent Current LDO Regulator, 8-Pin SOIC 150mil, Extended Temperature, Tape and Reel
footprint SOIC-SN8_N (SOIC, 8-Leads, Body 4.9x3.8mm, Pitch 1.27mm, IPC Medium Density)
footprint SOIC-SN8_L (SOIC, 8-Leads, Body 4.9x3.8mm, Pitch 1.27mm, IPC High Density)
footprint SOIC-SN8_M (SOIC, 8-Leads, Body 4.9x3.8mm, Pitch 1.27mm, IPC Low Density)
pins: 1 VIN (power), 2 VIN (power), 3 ~{SHDN} (in), 4 GND (power), 5 PWRGD (power), 6 CDELAY, 7 SENSE, 8 VOUT (power)

## MCP1725T-ADJE/MC
designator U?
500 mA, Low Voltage, Low Quiescent Current LDO Regulator, 8-Pin DFN, Extended Temperature, Tape and Reel
footprint DFN-MC8 (SON, 8-Leads, Body 2x3mm, Pitch 0.5mm, Microchip Recommended)
pins: 1 VIN (power), 2 VIN (power), 3 ~{SHDN} (in), 4 GND (power), 5 PWRGD (power), 6 CDELAY, 7 ADJ (in), 8 VOUT (power), 9 EP (power)

## MCP1725T-ADJE/SN
designator U?
500 mA, Low Voltage, Low Quiescent Current LDO Regulator, 8-Pin SOIC 150mil, Extended Temperature, Tape and Reel
footprint SOIC-SN8_N (SOIC, 8-Leads, Body 4.9x3.8mm, Pitch 1.27mm, IPC Medium Density)
footprint SOIC-SN8_L (SOIC, 8-Leads, Body 4.9x3.8mm, Pitch 1.27mm, IPC High Density)
footprint SOIC-SN8_M (SOIC, 8-Leads, Body 4.9x3.8mm, Pitch 1.27mm, IPC Low Density)
pins: 1 VIN (power), 2 VIN (power), 3 ~{SHDN} (in), 4 GND (power), 5 PWRGD (power), 6 CDELAY, 7 ADJ (in), 8 VOUT (power)

## MCP1726-0802E/MF
designator U?
1A, Low Voltage, Low Quiescent Current LDO Regulator, 8-Pin DFN, Extended Temperature
footprint DFN-MF8 (SON, 8-Leads, Body 3x3mm, Pitch 0.65mm, Microchip Recommended)
pins: 1 VIN (power), 2 VIN (power), 3 ~{SHDN} (in), 4 GND (power), 5 PWRGD (power), 6 CDELAY, 7 VOUT (power), 8 VOUT (power), 9 EP (power)

## MCP1726-0802E/SN
designator U?
1A, Low Voltage, Low Quiescent Current LDO Regulator, 8-Pin SOIC 150mil, Extended Temperature
footprint SOIC-SN8_N (SOIC, 8-Leads, Body 4.9x3.8mm, Pitch 1.27mm, IPC Medium Density)
footprint SOIC-SN8_L (SOIC, 8-Leads, Body 4.9x3.8mm, Pitch 1.27mm, IPC High Density)
footprint SOIC-SN8_M (SOIC, 8-Leads, Body 4.9x3.8mm, Pitch 1.27mm, IPC Low Density)
pins: 1 VIN (power), 2 VIN (power), 3 ~{SHDN} (in), 4 GND (power), 5 PWRGD (power), 6 CDELAY, 7 VOUT (power), 8 VOUT (power)

## MCP1726-1202E/MF
designator U?
1A, Low Voltage, Low Quiescent Current LDO Regulator, 8-Pin DFN, Extended Temperature
footprint DFN-MF8 (SON, 8-Leads, Body 3x3mm, Pitch 0.65mm, Microchip Recommended)
pins: 1 VIN (power), 2 VIN (power), 3 ~{SHDN} (in), 4 GND (power), 5 PWRGD (power), 6 CDELAY, 7 VOUT (power), 8 VOUT (power), 9 EP (power)

## MCP1726-1202E/SN
designator U?
1A, Low Voltage, Low Quiescent Current LDO Regulator, 8-Pin SOIC 150mil, Extended Temperature
footprint SOIC-SN8_N (SOIC, 8-Leads, Body 4.9x3.8mm, Pitch 1.27mm, IPC Medium Density)
footprint SOIC-SN8_L (SOIC, 8-Leads, Body 4.9x3.8mm, Pitch 1.27mm, IPC High Density)
footprint SOIC-SN8_M (SOIC, 8-Leads, Body 4.9x3.8mm, Pitch 1.27mm, IPC Low Density)
pins: 1 VIN (power), 2 VIN (power), 3 ~{SHDN} (in), 4 GND (power), 5 PWRGD (power), 6 CDELAY, 7 VOUT (power), 8 VOUT (power)

## MCP1726-1802E/MF
designator U?
1A, Low Voltage, Low Quiescent Current LDO Regulator, 8-Pin DFN, Extended Temperature
footprint DFN-MF8 (SON, 8-Leads, Body 3x3mm, Pitch 0.65mm, Microchip Recommended)
pins: 1 VIN (power), 2 VIN (power), 3 ~{SHDN} (in), 4 GND (power), 5 PWRGD (power), 6 CDELAY, 7 VOUT (power), 8 VOUT (power), 9 EP (power)

## MCP1726-1802E/SN
designator U?
1A, Low Voltage, Low Quiescent Current LDO Regulator, 8-Pin SOIC 150mil, Extended Temperature
footprint SOIC-SN8_N (SOIC, 8-Leads, Body 4.9x3.8mm, Pitch 1.27mm, IPC Medium Density)
footprint SOIC-SN8_L (SOIC, 8-Leads, Body 4.9x3.8mm, Pitch 1.27mm, IPC High Density)
footprint SOIC-SN8_M (SOIC, 8-Leads, Body 4.9x3.8mm, Pitch 1.27mm, IPC Low Density)
pins: 1 VIN (power), 2 VIN (power), 3 ~{SHDN} (in), 4 GND (power), 5 PWRGD (power), 6 CDELAY, 7 VOUT (power), 8 VOUT (power)

## MCP1726-2502E/MF
designator U?
1A, Low Voltage, Low Quiescent Current LDO Regulator, 8-Pin DFN, Extended Temperature
footprint DFN-MF8 (SON, 8-Leads, Body 3x3mm, Pitch 0.65mm, Microchip Recommended)
pins: 1 VIN (power), 2 VIN (power), 3 ~{SHDN} (in), 4 GND (power), 5 PWRGD (power), 6 CDELAY, 7 VOUT (power), 8 VOUT (power), 9 EP (power)

## MCP1726-2502E/SN
designator U?
1A, Low Voltage, Low Quiescent Current LDO Regulator, 8-Pin SOIC 150mil, Extended Temperature
footprint SOIC-SN8_N (SOIC, 8-Leads, Body 4.9x3.8mm, Pitch 1.27mm, IPC Medium Density)
footprint SOIC-SN8_L (SOIC, 8-Leads, Body 4.9x3.8mm, Pitch 1.27mm, IPC High Density)
footprint SOIC-SN8_M (SOIC, 8-Leads, Body 4.9x3.8mm, Pitch 1.27mm, IPC Low Density)
pins: 1 VIN (power), 2 VIN (power), 3 ~{SHDN} (in), 4 GND (power), 5 PWRGD (power), 6 CDELAY, 7 VOUT (power), 8 VOUT (power)

## MCP1726-3002E/MF
designator U?
1A, Low Voltage, Low Quiescent Current LDO Regulator, 8-Pin DFN, Extended Temperature
footprint DFN-MF8 (SON, 8-Leads, Body 3x3mm, Pitch 0.65mm, Microchip Recommended)
pins: 1 VIN (power), 2 VIN (power), 3 ~{SHDN} (in), 4 GND (power), 5 PWRGD (power), 6 CDELAY, 7 VOUT (power), 8 VOUT (power), 9 EP (power)

## MCP1726-3002E/SN
designator U?
1A, Low Voltage, Low Quiescent Current LDO Regulator, 8-Pin SOIC 150mil, Extended Temperature
footprint SOIC-SN8_N (SOIC, 8-Leads, Body 4.9x3.8mm, Pitch 1.27mm, IPC Medium Density)
footprint SOIC-SN8_L (SOIC, 8-Leads, Body 4.9x3.8mm, Pitch 1.27mm, IPC High Density)
footprint SOIC-SN8_M (SOIC, 8-Leads, Body 4.9x3.8mm, Pitch 1.27mm, IPC Low Density)
pins: 1 VIN (power), 2 VIN (power), 3 ~{SHDN} (in), 4 GND (power), 5 PWRGD (power), 6 CDELAY, 7 VOUT (power), 8 VOUT (power)

## MCP1726-3302E/MF
designator U?
1A, Low Voltage, Low Quiescent Current LDO Regulator, 8-Pin DFN, Extended Temperature
footprint DFN-MF8 (SON, 8-Leads, Body 3x3mm, Pitch 0.65mm, Microchip Recommended)
pins: 1 VIN (power), 2 VIN (power), 3 ~{SHDN} (in), 4 GND (power), 5 PWRGD (power), 6 CDELAY, 7 VOUT (power), 8 VOUT (power), 9 EP (power)

## MCP1726-3302E/SN
designator U?
1A, Low Voltage, Low Quiescent Current LDO Regulator, 8-Pin SOIC 150mil, Extended Temperature
footprint SOIC-SN8_N (SOIC, 8-Leads, Body 4.9x3.8mm, Pitch 1.27mm, IPC Medium Density)
footprint SOIC-SN8_L (SOIC, 8-Leads, Body 4.9x3.8mm, Pitch 1.27mm, IPC High Density)
footprint SOIC-SN8_M (SOIC, 8-Leads, Body 4.9x3.8mm, Pitch 1.27mm, IPC Low Density)
pins: 1 VIN (power), 2 VIN (power), 3 ~{SHDN} (in), 4 GND (power), 5 PWRGD (power), 6 CDELAY, 7 VOUT (power), 8 VOUT (power)

## MCP1726-5002E/MF
designator U?
1A, Low Voltage, Low Quiescent Current LDO Regulator, 8-Pin DFN, Extended Temperature
footprint DFN-MF8 (SON, 8-Leads, Body 3x3mm, Pitch 0.65mm, Microchip Recommended)
pins: 1 VIN (power), 2 VIN (power), 3 ~{SHDN} (in), 4 GND (power), 5 PWRGD (power), 6 CDELAY, 7 VOUT (power), 8 VOUT (power), 9 EP (power)

## MCP1726-5002E/SN
designator U?
1A, Low Voltage, Low Quiescent Current LDO Regulator, 8-Pin SOIC 150mil, Extended Temperature
footprint SOIC-SN8_N (SOIC, 8-Leads, Body 4.9x3.8mm, Pitch 1.27mm, IPC Medium Density)
footprint SOIC-SN8_L (SOIC, 8-Leads, Body 4.9x3.8mm, Pitch 1.27mm, IPC High Density)
footprint SOIC-SN8_M (SOIC, 8-Leads, Body 4.9x3.8mm, Pitch 1.27mm, IPC Low Density)
pins: 1 VIN (power), 2 VIN (power), 3 ~{SHDN} (in), 4 GND (power), 5 PWRGD (power), 6 CDELAY, 7 VOUT (power), 8 VOUT (power)

## MCP1726-ADJE/MF
designator U?
1A, Low Voltage, Low Quiescent Current LDO Regulator, 8-Pin DFN, Extended Temperature
footprint DFN-MF8 (SON, 8-Leads, Body 3x3mm, Pitch 0.65mm, Microchip Recommended)
pins: 1 VIN (power), 2 VIN (power), 3 ~{SHDN} (in), 4 GND (power), 5 PWRGD (power), 6 CDELAY, 7 ADJ (in), 8 VOUT (power), 9 EP (power)

## MCP1726-ADJE/SN
designator U?
1A, Low Voltage, Low Quiescent Current LDO Regulator, 8-Pin SOIC 150mil, Extended Temperature
footprint SOIC-SN8_N (SOIC, 8-Leads, Body 4.9x3.8mm, Pitch 1.27mm, IPC Medium Density)
footprint SOIC-SN8_L (SOIC, 8-Leads, Body 4.9x3.8mm, Pitch 1.27mm, IPC High Density)
footprint SOIC-SN8_M (SOIC, 8-Leads, Body 4.9x3.8mm, Pitch 1.27mm, IPC Low Density)
pins: 1 VIN (power), 2 VIN (power), 3 ~{SHDN} (in), 4 GND (power), 5 PWRGD (power), 6 CDELAY, 7 ADJ (in), 8 VOUT (power)

## MCP1726T-0802E/MF
designator U?
1A, Low Voltage, Low Quiescent Current LDO Regulator, 8-Pin DFN, Extended Temperature, Tape and Reel
footprint DFN-MF8 (SON, 8-Leads, Body 3x3mm, Pitch 0.65mm, Microchip Recommended)
pins: 1 VIN (power), 2 VIN (power), 3 ~{SHDN} (in), 4 GND (power), 5 PWRGD (power), 6 CDELAY, 7 VOUT (power), 8 VOUT (power), 9 EP (power)

## MCP1726T-0802E/SN
designator U?
1A, Low Voltage, Low Quiescent Current LDO Regulator, 8-Pin SOIC 150mil, Extended Temperature, Tape and Reel
footprint SOIC-SN8_N (SOIC, 8-Leads, Body 4.9x3.8mm, Pitch 1.27mm, IPC Medium Density)
footprint SOIC-SN8_L (SOIC, 8-Leads, Body 4.9x3.8mm, Pitch 1.27mm, IPC High Density)
footprint SOIC-SN8_M (SOIC, 8-Leads, Body 4.9x3.8mm, Pitch 1.27mm, IPC Low Density)
pins: 1 VIN (power), 2 VIN (power), 3 ~{SHDN} (in), 4 GND (power), 5 PWRGD (power), 6 CDELAY, 7 VOUT (power), 8 VOUT (power)

## MCP1726T-1202E/MF
designator U?
1A, Low Voltage, Low Quiescent Current LDO Regulator, 8-Pin DFN, Extended Temperature, Tape and Reel
footprint DFN-MF8 (SON, 8-Leads, Body 3x3mm, Pitch 0.65mm, Microchip Recommended)
pins: 1 VIN (power), 2 VIN (power), 3 ~{SHDN} (in), 4 GND (power), 5 PWRGD (power), 6 CDELAY, 7 VOUT (power), 8 VOUT (power), 9 EP (power)

## MCP1726T-1202E/SN
designator U?
1A, Low Voltage, Low Quiescent Current LDO Regulator, 8-Pin SOIC 150mil, Extended Temperature, Tape and Reel
footprint SOIC-SN8_N (SOIC, 8-Leads, Body 4.9x3.8mm, Pitch 1.27mm, IPC Medium Density)
footprint SOIC-SN8_L (SOIC, 8-Leads, Body 4.9x3.8mm, Pitch 1.27mm, IPC High Density)
footprint SOIC-SN8_M (SOIC, 8-Leads, Body 4.9x3.8mm, Pitch 1.27mm, IPC Low Density)
pins: 1 VIN (power), 2 VIN (power), 3 ~{SHDN} (in), 4 GND (power), 5 PWRGD (power), 6 CDELAY, 7 VOUT (power), 8 VOUT (power)

## MCP1726T-1802E/MF
designator U?
1A, Low Voltage, Low Quiescent Current LDO Regulator, 8-Pin DFN, Extended Temperature, Tape and Reel
footprint DFN-MF8 (SON, 8-Leads, Body 3x3mm, Pitch 0.65mm, Microchip Recommended)
pins: 1 VIN (power), 2 VIN (power), 3 ~{SHDN} (in), 4 GND (power), 5 PWRGD (power), 6 CDELAY, 7 VOUT (power), 8 VOUT (power), 9 EP (power)

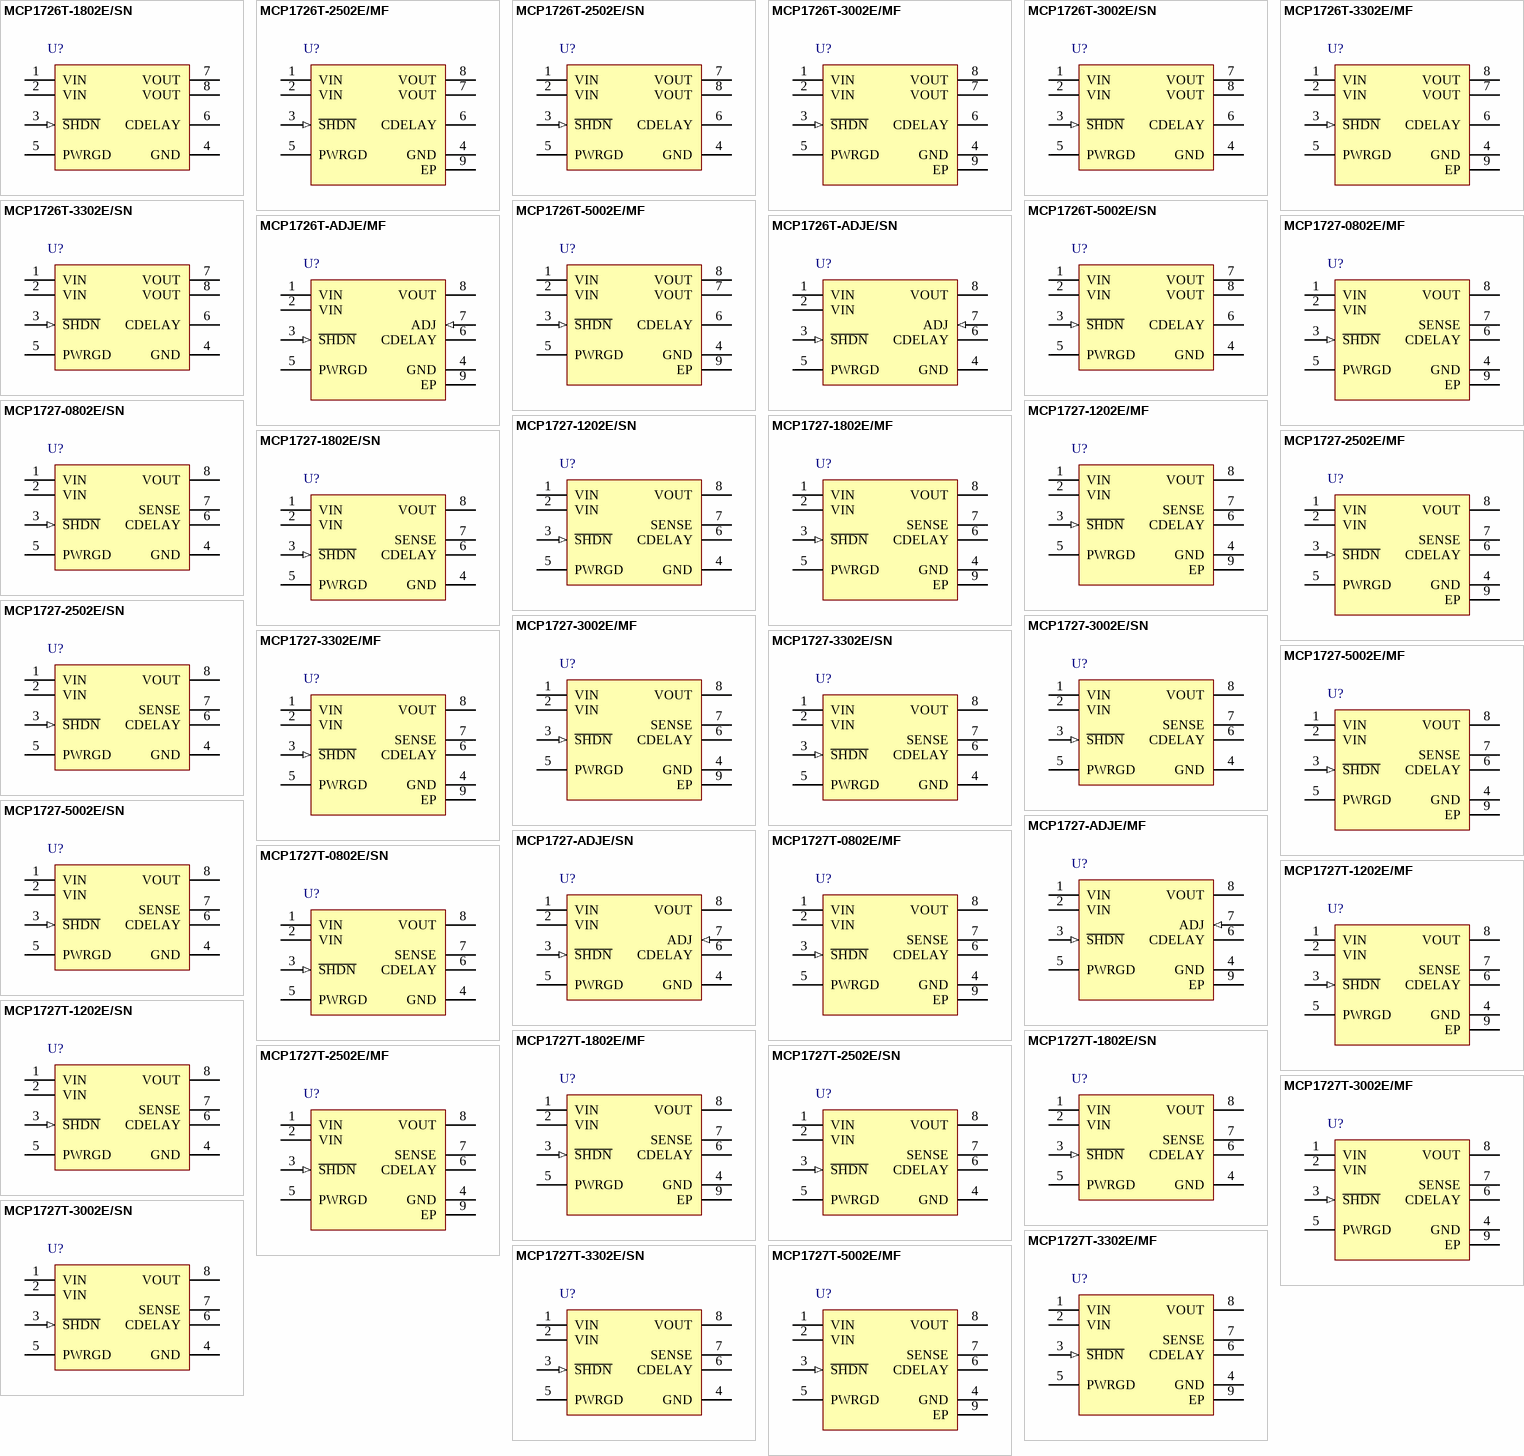
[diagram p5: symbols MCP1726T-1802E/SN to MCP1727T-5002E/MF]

## MCP1726T-1802E/SN
designator U?
1A, Low Voltage, Low Quiescent Current LDO Regulator, 8-Pin SOIC 150mil, Extended Temperature, Tape and Reel
footprint SOIC-SN8_N (SOIC, 8-Leads, Body 4.9x3.8mm, Pitch 1.27mm, IPC Medium Density)
footprint SOIC-SN8_L (SOIC, 8-Leads, Body 4.9x3.8mm, Pitch 1.27mm, IPC High Density)
footprint SOIC-SN8_M (SOIC, 8-Leads, Body 4.9x3.8mm, Pitch 1.27mm, IPC Low Density)
pins: 1 VIN (power), 2 VIN (power), 3 ~{SHDN} (in), 4 GND (power), 5 PWRGD (power), 6 CDELAY, 7 VOUT (power), 8 VOUT (power)

## MCP1726T-2502E/MF
designator U?
1A, Low Voltage, Low Quiescent Current LDO Regulator, 8-Pin DFN, Extended Temperature, Tape and Reel
footprint DFN-MF8 (SON, 8-Leads, Body 3x3mm, Pitch 0.65mm, Microchip Recommended)
pins: 1 VIN (power), 2 VIN (power), 3 ~{SHDN} (in), 4 GND (power), 5 PWRGD (power), 6 CDELAY, 7 VOUT (power), 8 VOUT (power), 9 EP (power)

## MCP1726T-2502E/SN
designator U?
1A, Low Voltage, Low Quiescent Current LDO Regulator, 8-Pin SOIC 150mil, Extended Temperature, Tape and Reel
footprint SOIC-SN8_N (SOIC, 8-Leads, Body 4.9x3.8mm, Pitch 1.27mm, IPC Medium Density)
footprint SOIC-SN8_L (SOIC, 8-Leads, Body 4.9x3.8mm, Pitch 1.27mm, IPC High Density)
footprint SOIC-SN8_M (SOIC, 8-Leads, Body 4.9x3.8mm, Pitch 1.27mm, IPC Low Density)
pins: 1 VIN (power), 2 VIN (power), 3 ~{SHDN} (in), 4 GND (power), 5 PWRGD (power), 6 CDELAY, 7 VOUT (power), 8 VOUT (power)

## MCP1726T-3002E/MF
designator U?
1A, Low Voltage, Low Quiescent Current LDO Regulator, 8-Pin DFN, Extended Temperature, Tape and Reel
footprint DFN-MF8 (SON, 8-Leads, Body 3x3mm, Pitch 0.65mm, Microchip Recommended)
pins: 1 VIN (power), 2 VIN (power), 3 ~{SHDN} (in), 4 GND (power), 5 PWRGD (power), 6 CDELAY, 7 VOUT (power), 8 VOUT (power), 9 EP (power)

## MCP1726T-3002E/SN
designator U?
1A, Low Voltage, Low Quiescent Current LDO Regulator, 8-Pin SOIC 150mil, Extended Temperature, Tape and Reel
footprint SOIC-SN8_N (SOIC, 8-Leads, Body 4.9x3.8mm, Pitch 1.27mm, IPC Medium Density)
footprint SOIC-SN8_L (SOIC, 8-Leads, Body 4.9x3.8mm, Pitch 1.27mm, IPC High Density)
footprint SOIC-SN8_M (SOIC, 8-Leads, Body 4.9x3.8mm, Pitch 1.27mm, IPC Low Density)
pins: 1 VIN (power), 2 VIN (power), 3 ~{SHDN} (in), 4 GND (power), 5 PWRGD (power), 6 CDELAY, 7 VOUT (power), 8 VOUT (power)

## MCP1726T-3302E/MF
designator U?
1A, Low Voltage, Low Quiescent Current LDO Regulator, 8-Pin DFN, Extended Temperature, Tape and Reel
footprint DFN-MF8 (SON, 8-Leads, Body 3x3mm, Pitch 0.65mm, Microchip Recommended)
pins: 1 VIN (power), 2 VIN (power), 3 ~{SHDN} (in), 4 GND (power), 5 PWRGD (power), 6 CDELAY, 7 VOUT (power), 8 VOUT (power), 9 EP (power)

## MCP1726T-3302E/SN
designator U?
1A, Low Voltage, Low Quiescent Current LDO Regulator, 8-Pin SOIC 150mil, Extended Temperature, Tape and Reel
footprint SOIC-SN8_N (SOIC, 8-Leads, Body 4.9x3.8mm, Pitch 1.27mm, IPC Medium Density)
footprint SOIC-SN8_L (SOIC, 8-Leads, Body 4.9x3.8mm, Pitch 1.27mm, IPC High Density)
footprint SOIC-SN8_M (SOIC, 8-Leads, Body 4.9x3.8mm, Pitch 1.27mm, IPC Low Density)
pins: 1 VIN (power), 2 VIN (power), 3 ~{SHDN} (in), 4 GND (power), 5 PWRGD (power), 6 CDELAY, 7 VOUT (power), 8 VOUT (power)

## MCP1726T-5002E/MF
designator U?
1A, Low Voltage, Low Quiescent Current LDO Regulator, 8-Pin DFN, Extended Temperature, Tape and Reel
footprint DFN-MF8 (SON, 8-Leads, Body 3x3mm, Pitch 0.65mm, Microchip Recommended)
pins: 1 VIN (power), 2 VIN (power), 3 ~{SHDN} (in), 4 GND (power), 5 PWRGD (power), 6 CDELAY, 7 VOUT (power), 8 VOUT (power), 9 EP (power)

## MCP1726T-5002E/SN
designator U?
1A, Low Voltage, Low Quiescent Current LDO Regulator, 8-Pin SOIC 150mil, Extended Temperature, Tape and Reel
footprint SOIC-SN8_N (SOIC, 8-Leads, Body 4.9x3.8mm, Pitch 1.27mm, IPC Medium Density)
footprint SOIC-SN8_L (SOIC, 8-Leads, Body 4.9x3.8mm, Pitch 1.27mm, IPC High Density)
footprint SOIC-SN8_M (SOIC, 8-Leads, Body 4.9x3.8mm, Pitch 1.27mm, IPC Low Density)
pins: 1 VIN (power), 2 VIN (power), 3 ~{SHDN} (in), 4 GND (power), 5 PWRGD (power), 6 CDELAY, 7 VOUT (power), 8 VOUT (power)

## MCP1726T-ADJE/MF
designator U?
1A, Low Voltage, Low Quiescent Current LDO Regulator, 8-Pin DFN, Extended Temperature, Tape and Reel
footprint DFN-MF8 (SON, 8-Leads, Body 3x3mm, Pitch 0.65mm, Microchip Recommended)
pins: 1 VIN (power), 2 VIN (power), 3 ~{SHDN} (in), 4 GND (power), 5 PWRGD (power), 6 CDELAY, 7 ADJ (in), 8 VOUT (power), 9 EP (power)

## MCP1726T-ADJE/SN
designator U?
1A, Low Voltage, Low Quiescent Current LDO Regulator, 8-Pin SOIC 150mil, Extended Temperature, Tape and Reel
footprint SOIC-SN8_N (SOIC, 8-Leads, Body 4.9x3.8mm, Pitch 1.27mm, IPC Medium Density)
footprint SOIC-SN8_L (SOIC, 8-Leads, Body 4.9x3.8mm, Pitch 1.27mm, IPC High Density)
footprint SOIC-SN8_M (SOIC, 8-Leads, Body 4.9x3.8mm, Pitch 1.27mm, IPC Low Density)
pins: 1 VIN (power), 2 VIN (power), 3 ~{SHDN} (in), 4 GND (power), 5 PWRGD (power), 6 CDELAY, 7 ADJ (in), 8 VOUT (power)

## MCP1727-0802E/MF
designator U?
1.5A, Low Voltage, Low Quiescent Current LDO Regulator, 8-Pin DFN, Extended Temperature
footprint DFN-MF8 (SON, 8-Leads, Body 3x3mm, Pitch 0.65mm, Microchip Recommended)
pins: 1 VIN (power), 2 VIN (power), 3 ~{SHDN} (in), 4 GND (power), 5 PWRGD (power), 6 CDELAY, 7 SENSE, 8 VOUT (power), 9 EP (power)

## MCP1727-0802E/SN
designator U?
1.5A, Low Voltage, Low Quiescent Current LDO Regulator, 8-Pin SOIC 150mil, Extended Temperature
footprint SOIC-SN8_N (SOIC, 8-Leads, Body 4.9x3.8mm, Pitch 1.27mm, IPC Medium Density)
footprint SOIC-SN8_L (SOIC, 8-Leads, Body 4.9x3.8mm, Pitch 1.27mm, IPC High Density)
footprint SOIC-SN8_M (SOIC, 8-Leads, Body 4.9x3.8mm, Pitch 1.27mm, IPC Low Density)
pins: 1 VIN (power), 2 VIN (power), 3 ~{SHDN} (in), 4 GND (power), 5 PWRGD (power), 6 CDELAY, 7 SENSE, 8 VOUT (power)

## MCP1727-1202E/MF
designator U?
1.5A, Low Voltage, Low Quiescent Current LDO Regulator, 8-Pin DFN, Extended Temperature
footprint DFN-MF8 (SON, 8-Leads, Body 3x3mm, Pitch 0.65mm, Microchip Recommended)
pins: 1 VIN (power), 2 VIN (power), 3 ~{SHDN} (in), 4 GND (power), 5 PWRGD (power), 6 CDELAY, 7 SENSE, 8 VOUT (power), 9 EP (power)

## MCP1727-1202E/SN
designator U?
1.5A, Low Voltage, Low Quiescent Current LDO Regulator, 8-Pin SOIC 150mil, Extended Temperature
footprint SOIC-SN8_N (SOIC, 8-Leads, Body 4.9x3.8mm, Pitch 1.27mm, IPC Medium Density)
footprint SOIC-SN8_L (SOIC, 8-Leads, Body 4.9x3.8mm, Pitch 1.27mm, IPC High Density)
footprint SOIC-SN8_M (SOIC, 8-Leads, Body 4.9x3.8mm, Pitch 1.27mm, IPC Low Density)
pins: 1 VIN (power), 2 VIN (power), 3 ~{SHDN} (in), 4 GND (power), 5 PWRGD (power), 6 CDELAY, 7 SENSE, 8 VOUT (power)

## MCP1727-1802E/MF
designator U?
1.5A, Low Voltage, Low Quiescent Current LDO Regulator, 8-Pin DFN, Extended Temperature
footprint DFN-MF8 (SON, 8-Leads, Body 3x3mm, Pitch 0.65mm, Microchip Recommended)
pins: 1 VIN (power), 2 VIN (power), 3 ~{SHDN} (in), 4 GND (power), 5 PWRGD (power), 6 CDELAY, 7 SENSE, 8 VOUT (power), 9 EP (power)

## MCP1727-1802E/SN
designator U?
1.5A, Low Voltage, Low Quiescent Current LDO Regulator, 8-Pin SOIC 150mil, Extended Temperature
footprint SOIC-SN8_N (SOIC, 8-Leads, Body 4.9x3.8mm, Pitch 1.27mm, IPC Medium Density)
footprint SOIC-SN8_L (SOIC, 8-Leads, Body 4.9x3.8mm, Pitch 1.27mm, IPC High Density)
footprint SOIC-SN8_M (SOIC, 8-Leads, Body 4.9x3.8mm, Pitch 1.27mm, IPC Low Density)
pins: 1 VIN (power), 2 VIN (power), 3 ~{SHDN} (in), 4 GND (power), 5 PWRGD (power), 6 CDELAY, 7 SENSE, 8 VOUT (power)

## MCP1727-2502E/MF
designator U?
1.5A, Low Voltage, Low Quiescent Current LDO Regulator, 8-Pin DFN, Extended Temperature
footprint DFN-MF8 (SON, 8-Leads, Body 3x3mm, Pitch 0.65mm, Microchip Recommended)
pins: 1 VIN (power), 2 VIN (power), 3 ~{SHDN} (in), 4 GND (power), 5 PWRGD (power), 6 CDELAY, 7 SENSE, 8 VOUT (power), 9 EP (power)

## MCP1727-2502E/SN
designator U?
1.5A, Low Voltage, Low Quiescent Current LDO Regulator, 8-Pin SOIC 150mil, Extended Temperature
footprint SOIC-SN8_N (SOIC, 8-Leads, Body 4.9x3.8mm, Pitch 1.27mm, IPC Medium Density)
footprint SOIC-SN8_L (SOIC, 8-Leads, Body 4.9x3.8mm, Pitch 1.27mm, IPC High Density)
footprint SOIC-SN8_M (SOIC, 8-Leads, Body 4.9x3.8mm, Pitch 1.27mm, IPC Low Density)
pins: 1 VIN (power), 2 VIN (power), 3 ~{SHDN} (in), 4 GND (power), 5 PWRGD (power), 6 CDELAY, 7 SENSE, 8 VOUT (power)

## MCP1727-3002E/MF
designator U?
1.5A, Low Voltage, Low Quiescent Current LDO Regulator, 8-Pin DFN, Extended Temperature
footprint DFN-MF8 (SON, 8-Leads, Body 3x3mm, Pitch 0.65mm, Microchip Recommended)
pins: 1 VIN (power), 2 VIN (power), 3 ~{SHDN} (in), 4 GND (power), 5 PWRGD (power), 6 CDELAY, 7 SENSE, 8 VOUT (power), 9 EP (power)

## MCP1727-3002E/SN
designator U?
1.5A, Low Voltage, Low Quiescent Current LDO Regulator, 8-Pin SOIC 150mil, Extended Temperature
footprint SOIC-SN8_N (SOIC, 8-Leads, Body 4.9x3.8mm, Pitch 1.27mm, IPC Medium Density)
footprint SOIC-SN8_L (SOIC, 8-Leads, Body 4.9x3.8mm, Pitch 1.27mm, IPC High Density)
footprint SOIC-SN8_M (SOIC, 8-Leads, Body 4.9x3.8mm, Pitch 1.27mm, IPC Low Density)
pins: 1 VIN (power), 2 VIN (power), 3 ~{SHDN} (in), 4 GND (power), 5 PWRGD (power), 6 CDELAY, 7 SENSE, 8 VOUT (power)

## MCP1727-3302E/MF
designator U?
1.5A, Low Voltage, Low Quiescent Current LDO Regulator, 8-Pin DFN, Extended Temperature
footprint DFN-MF8 (SON, 8-Leads, Body 3x3mm, Pitch 0.65mm, Microchip Recommended)
pins: 1 VIN (power), 2 VIN (power), 3 ~{SHDN} (in), 4 GND (power), 5 PWRGD (power), 6 CDELAY, 7 SENSE, 8 VOUT (power), 9 EP (power)

## MCP1727-3302E/SN
designator U?
1.5A, Low Voltage, Low Quiescent Current LDO Regulator, 8-Pin SOIC 150mil, Extended Temperature
footprint SOIC-SN8_N (SOIC, 8-Leads, Body 4.9x3.8mm, Pitch 1.27mm, IPC Medium Density)
footprint SOIC-SN8_L (SOIC, 8-Leads, Body 4.9x3.8mm, Pitch 1.27mm, IPC High Density)
footprint SOIC-SN8_M (SOIC, 8-Leads, Body 4.9x3.8mm, Pitch 1.27mm, IPC Low Density)
pins: 1 VIN (power), 2 VIN (power), 3 ~{SHDN} (in), 4 GND (power), 5 PWRGD (power), 6 CDELAY, 7 SENSE, 8 VOUT (power)

## MCP1727-5002E/MF
designator U?
1.5A, Low Voltage, Low Quiescent Current LDO Regulator, 8-Pin DFN, Extended Temperature
footprint DFN-MF8 (SON, 8-Leads, Body 3x3mm, Pitch 0.65mm, Microchip Recommended)
pins: 1 VIN (power), 2 VIN (power), 3 ~{SHDN} (in), 4 GND (power), 5 PWRGD (power), 6 CDELAY, 7 SENSE, 8 VOUT (power), 9 EP (power)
